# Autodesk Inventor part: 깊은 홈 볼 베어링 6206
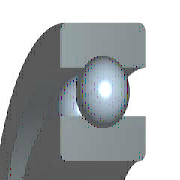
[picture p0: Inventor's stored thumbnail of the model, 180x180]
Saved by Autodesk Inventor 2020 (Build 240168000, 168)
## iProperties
Created: 2012-02
Part Number: 깊은 홈 볼 베어링 6206
Material: 강철, 연강
Description: 깊은 그루부 볼 베어링
Document SubType Name: Modeling
Standard: JIS B 1521
Designer: mdu-01
Standards Organization: JIS
Language: ko-KR
Size Designation: 6206 30x62x16
Categories: <MemberInstance><Categories><Category DisplayName="샤프트 부품" InternalName="7f7aeb1f-a693-4053-b835-cee3144e0d98" Mnemonic="SHFT"><Category DisplayName="베어링" Inter
Density: 1 g/cm^3
Appearance: 강철(1)
IsCustomPart: 1
Author: mdu-01
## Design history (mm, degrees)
sketch "스케치" dims "d0" = 8.32 (= -0.26 x WD + 0.26 x BD)
  geometry: L1 (3.84, 23)-(12.16, 23); L2 (8, 23)-(8, 18.84); L3 (8, 23)-(8, 27.16); L4 (4.909, 20.216)-(0, 20.216); L5 (0, 15)-(16, 15); L6 (4.909, 25.784)-(0, 25.784); L7 (0, 31)-(16, 31); L8 (16, 15)-(16, 20.216); L9 (11.091, 20.216)-(16, 20.216); L10 (11.091, 25.784)-(16, 25.784); L11 (16, 31)-(16, 25.784); L12 (-1.4, 0)-(8.4, 0) reference; L13 (0, -0.3)-(0, 5.3) reference
  constraints: 22 end point, 4 point on line, 2 collinear, 2 perpendicular, 2 symmetric about line, 1 midpoint, 1 parallel, 14 other
  dimensions: "d9" = 30 diameter of L5 L12 (= WD); "d11" = 62 diameter of L7 L12 (= BD); "d12" = 16 distance between parallel lines of L8 L13 (= KB); "d13" = 40.432 diameter of L9 L12 (= 0.326 x BD + 0.674 x WD)
revolve "본체" stored, may be unused: angle "d6" = 90 deg
revolve "볼" stored, may be unused: angle "d7" = 90 deg
pattern_circular "IDS_ARRAYBALL[SIMPL:T]" dims angle "d3" = 360 deg
body "Solid1"
fillet "모깎기1" dims "d1" = 1 (= KRS)
other parameters: "WD" = 30 [user parameter; used in 5 equation terms], "BD" = 62 [user parameter; used in 5 equation terms], "KB" = 16 [user parameter; used in 1 equation term], "KRS" = 1 [user parameter; used in 1 equation term], "d4" = 0, "d5" = 0, "d8" = 0, "d14" = 0, "d15" = 0, "BBA" = 0 [user parameter], "BC0" = 1.12e+07 [user parameter], "BC" = 1.95e+07 [user parameter], "BR" = 31 (= 0.5 x BD) [user parameter], "WR" = 15 (= 0.5 x WD) [user parameter]
